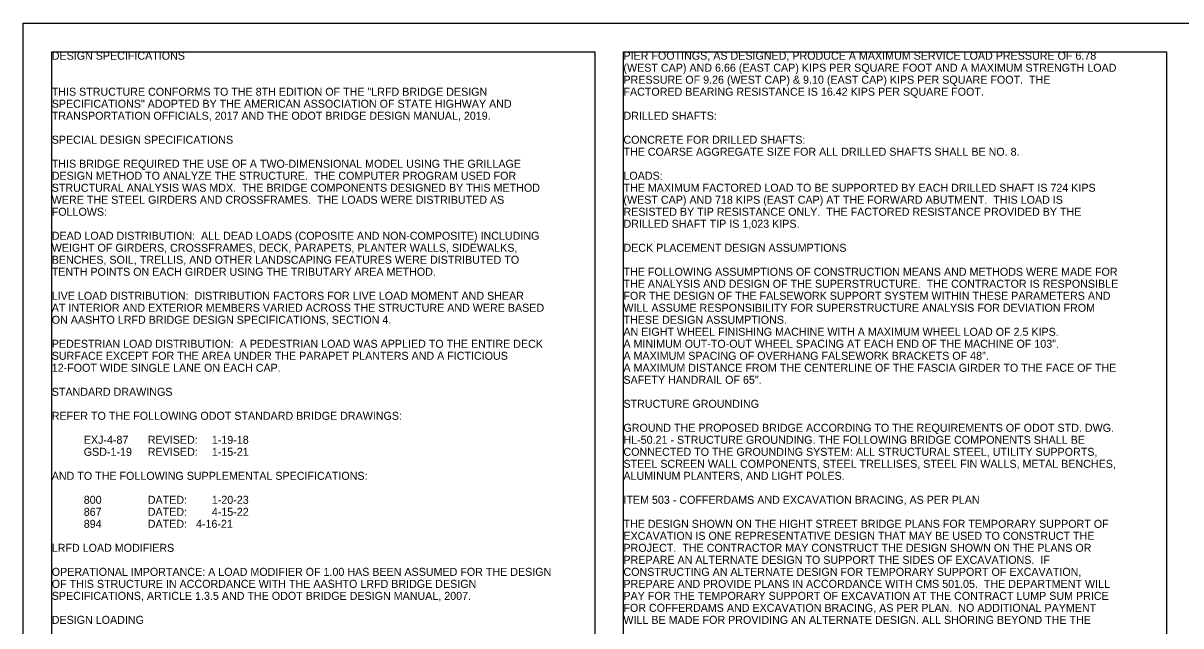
# Model space of a CAD drawing. Extents: x -27.4 to 41.5, y -43.2 to 24.4.
# Drawn here: x 1.24 to 21.49, y 8.71 to 19.26 of the extents above; entities that cross this region are included whole.
import ezdxf

# ---------------------------------------------------------------- set-up
doc = ezdxf.new("R2010")
doc.units = 0
for name, color, linetype in [('BR_P_Slab_Object', 7, 'Continuous'), ('BR_P_Sub_Foot_Hidden', 7, 'Continuous'), ('Default', 7, 'Continuous'), ('SH_Data', 7, 'Continuous')]:
    doc.layers.add(name, color=color, linetype=linetype)

msp = doc.modelspace()

# ---------------------------------------------------------------- linework, layer by layer
at = {"layer": 'BR_P_Slab_Object'}
for points in [[(1.744, 18.759), (11.244, 18.759), (11.244, -1.241), (1.744, -1.241)], [(11.744, 18.759), (21.244, 18.759), (21.244, -1.241), (11.744, -1.241)]]:
    msp.add_lwpolyline(points, close=True, dxfattribs=at)
at = {"layer": 'SH_Data'}
msp.add_lwpolyline([(1.244, 19.259), (31.744, 19.259), (31.744, -1.741), (1.244, -1.741)], close=True, dxfattribs=at)

# ---------------------------------------------------------------- texts
at = {"layer": 'BR_P_Sub_Foot_Hidden'}
for s, p in [('DESIGN SPECIFICATIONS', (1.744, 18.619)), ('PIER FOOTINGS, AS DESIGNED, PRODUCE A MAXIMUM SERVICE LOAD PRESSURE OF 6.78 ', (11.744, 18.619)), ('(WEST CAP) AND 6.66 (EAST CAP) KIPS PER SQUARE FOOT AND A MAXIMUM STRENGTH LOAD ', (11.744, 18.409)), ('PRESSURE OF 9.26 (WEST CAP) & 9.10 (EAST CAP) KIPS PER SQUARE FOOT.  THE ', (11.744, 18.199)), ('THIS STRUCTURE CONFORMS TO THE 8TH EDITION OF THE "LRFD BRIDGE DESIGN ', (1.744, 17.989)), ('FACTORED BEARING RESISTANCE IS 16.42 KIPS PER SQUARE FOOT.', (11.744, 17.989)), ('SPECIFICATIONS" ADOPTED BY THE AMERICAN ASSOCIATION OF STATE HIGHWAY AND ', (1.744, 17.779)), ('TRANSPORTATION OFFICIALS, 2017 AND THE ODOT BRIDGE DESIGN MANUAL, 2019.', (1.744, 17.569)), ('DRILLED SHAFTS:', (11.744, 17.569)), ('DRILLED SHAFTS:', (11.744, 17.569)), ('SPECIAL DESIGN SPECIFICATIONS', (1.744, 17.149)), ('SPECIAL DESIGN SPECIFICATIONS', (1.744, 17.149)), ('CONCRETE FOR DRILLED SHAFTS:', (11.744, 17.149)), ('THE COARSE AGGREGATE SIZE FOR ALL DRILLED SHAFTS SHALL BE NO. 8.', (11.744, 16.939)), ('THIS BRIDGE REQUIRED THE USE OF A TWO-DIMENSIONAL MODEL USING THE GRILLAGE ', (1.744, 16.729)), ('DESIGN METHOD TO ANALYZE THE STRUCTURE.  THE COMPUTER PROGRAM USED FOR ', (1.744, 16.519)), ('LOADS:', (11.744, 16.519)), ('STRUCTURAL ANALYSIS WAS MDX.  THE BRIDGE COMPONENTS DESIGNED BY THIS METHOD ', (1.744, 16.309)), ('THE MAXIMUM FACTORED LOAD TO BE SUPPORTED BY EACH DRILLED SHAFT IS 724 KIPS ', (11.744, 16.309)), ('WERE THE STEEL GIRDERS AND CROSSFRAMES.  THE LOADS WERE DISTRIBUTED AS ', (1.744, 16.099)), ('(WEST CAP) AND 718 KIPS (EAST CAP) AT THE FORWARD ABUTMENT.  THIS LOAD IS ', (11.744, 16.099)), ('FOLLOWS:', (1.744, 15.889)), ('RESISTED BY TIP RESISTANCE ONLY.  THE FACTORED RESISTANCE PROVIDED BY THE ', (11.744, 15.889)), ('DRILLED SHAFT TIP IS 1,023 KIPS.', (11.744, 15.679)), ('DEAD LOAD DISTRIBUTION:  ALL DEAD LOADS (COPOSITE AND NON-COMPOSITE) INCLUDING ', (1.744, 15.469)), ('WEIGHT OF GIRDERS, CROSSFRAMES, DECK, PARAPETS, PLANTER WALLS, SIDEWALKS, ', (1.744, 15.259)), ('DECK PLACEMENT DESIGN ASSUMPTIONS', (11.744, 15.259)), ('DECK PLACEMENT DESIGN ASSUMPTIONS', (11.744, 15.259)), ('BENCHES, SOIL, TRELLIS, AND OTHER LANDSCAPING FEATURES WERE DISTRIBUTED TO ', (1.744, 15.049)), ('TENTH POINTS ON EACH GIRDER USING THE TRIBUTARY AREA METHOD.  ', (1.744, 14.839)), ('THE FOLLOWING ASSUMPTIONS OF CONSTRUCTION MEANS AND METHODS WERE MADE FOR ', (11.744, 14.839)), ('THE ANALYSIS AND DESIGN OF THE SUPERSTRUCTURE.  THE CONTRACTOR IS RESPONSIBLE ', (11.744, 14.629)), ('LIVE LOAD DISTRIBUTION:  DISTRIBUTION FACTORS FOR LIVE LOAD MOMENT AND SHEAR ', (1.744, 14.419)), ('FOR THE DESIGN OF THE FALSEWORK SUPPORT SYSTEM WITHIN THESE PARAMETERS AND ', (11.744, 14.419)), ('AT INTERIOR AND EXTERIOR MEMBERS VARIED ACROSS THE STRUCTURE AND WERE BASED ', (1.744, 14.209)), ('WILL ASSUME RESPONSIBILITY FOR SUPERSTRUCTURE ANALYSIS FOR DEVIATION FROM ', (11.744, 14.209)), ('ON AASHTO LRFD BRIDGE DESIGN SPECIFICATIONS, SECTION 4.  ', (1.744, 13.999)), ('THESE DESIGN ASSUMPTIONS.', (11.744, 13.999)), ('AN EIGHT WHEEL FINISHING MACHINE WITH A MAXIMUM WHEEL LOAD OF 2.5 KIPS.', (11.744, 13.789)), ('PEDESTRIAN LOAD DISTRIBUTION:  A PEDESTRIAN LOAD WAS APPLIED TO THE ENTIRE DECK ', (1.744, 13.579)), ('A MINIMUM OUT-TO-OUT WHEEL SPACING AT EACH END OF THE MACHINE OF 103".', (11.744, 13.579)), ('SURFACE EXCEPT FOR THE AREA UNDER THE PARAPET PLANTERS AND A FICTICIOUS ', (1.744, 13.369)), ('A MAXIMUM SPACING OF OVERHANG FALSEWORK BRACKETS OF 48".', (11.744, 13.369)), ('12-FOOT WIDE SINGLE LANE ON EACH CAP.', (1.744, 13.159)), ('A MAXIMUM DISTANCE FROM THE CENTERLINE OF THE FASCIA GIRDER TO THE FACE OF THE ', (11.744, 13.159)), ('SAFETY HANDRAIL OF 65".', (11.744, 12.949)), ('STANDARD DRAWINGS', (1.744, 12.739)), ('STANDARD DRAWINGS', (1.744, 12.739)), ('STRUCTURE GROUNDING', (11.744, 12.529)), ('STRUCTURE GROUNDING', (11.744, 12.529)), ('REFER TO THE FOLLOWING ODOT STANDARD BRIDGE DRAWINGS:', (1.744, 12.319)), ('GROUND THE PROPOSED BRIDGE ACCORDING TO THE REQUIREMENTS OF ODOT STD. DWG. ', (11.744, 12.109)), ('EXJ-4-87 ', (2.304, 11.899)), ('REVISED: ', (3.424, 11.899)), ('1-19-18', (4.544, 11.899)), ('HL-50.21 - STRUCTURE GROUNDING. THE FOLLOWING BRIDGE COMPONENTS SHALL BE ', (11.744, 11.899)), ('GSD-1-19 ', (2.304, 11.689)), ('REVISED: ', (3.424, 11.689)), ('1-15-21', (4.544, 11.689)), ('CONNECTED TO THE GROUNDING SYSTEM: ALL STRUCTURAL STEEL, UTILITY SUPPORTS, ', (11.744, 11.689)), ('STEEL SCREEN WALL COMPONENTS, STEEL TRELLISES, STEEL FIN WALLS, METAL BENCHES, ', (11.744, 11.479)), ('AND TO THE FOLLOWING SUPPLEMENTAL SPECIFICATIONS:', (1.744, 11.269)), ('ALUMINUM PLANTERS, AND LIGHT POLES. ', (11.744, 11.269)), ('800', (2.304, 10.849)), ('DATED:', (3.424, 10.849)), ('1-20-23', (4.544, 10.849)), ('ITEM 503 - COFFERDAMS AND EXCAVATION BRACING, AS PER PLAN', (11.744, 10.849)), ('ITEM 503 - COFFERDAMS AND EXCAVATION BRACING, AS PER PLAN', (11.744, 10.849)), ('867', (2.304, 10.639)), ('DATED: ', (3.424, 10.639)), ('4-15-22', (4.544, 10.639)), ('894 ', (2.304, 10.429)), ('DATED:   4-16-21 ', (3.424, 10.429)), ('THE DESIGN SHOWN ON THE HIGHT STREET BRIDGE PLANS FOR TEMPORARY SUPPORT OF ', (11.744, 10.429)), ('EXCAVATION IS ONE REPRESENTATIVE DESIGN THAT MAY BE USED TO CONSTRUCT THE ', (11.744, 10.219)), ('LRFD LOAD MODIFIERS', (1.744, 10.009)), ('LRFD LOAD MODIFIERS', (1.744, 10.009)), ('PROJECT.  THE CONTRACTOR MAY CONSTRUCT THE DESIGN SHOWN ON THE PLANS OR ', (11.744, 10.009)), ('PREPARE AN ALTERNATE DESIGN TO SUPPORT THE SIDES OF EXCAVATIONS.  IF ', (11.744, 9.799)), ('OPERATIONAL IMPORTANCE: A LOAD MODIFIER OF 1.00 HAS BEEN ASSUMED FOR THE DESIGN ', (1.744, 9.589)), ('CONSTRUCTING AN ALTERNATE DESIGN FOR TEMPORARY SUPPORT OF EXCAVATION, ', (11.744, 9.589)), ('OF THIS STRUCTURE IN ACCORDANCE WITH THE AASHTO LRFD BRIDGE DESIGN ', (1.744, 9.379)), ('PREPARE AND PROVIDE PLANS IN ACCORDANCE WITH CMS 501.05.  THE DEPARTMENT WILL ', (11.744, 9.379)), ('SPECIFICATIONS, ARTICLE 1.3.5 AND THE ODOT BRIDGE DESIGN MANUAL, 2007.', (1.744, 9.169)), ('PAY FOR THE TEMPORARY SUPPORT OF EXCAVATION AT THE CONTRACT LUMP SUM PRICE ', (11.744, 9.169)), ('FOR COFFERDAMS AND EXCAVATION BRACING, AS PER PLAN.  NO ADDITIONAL PAYMENT ', (11.744, 8.959)), ('DESIGN LOADING', (1.744, 8.749)), ('DESIGN LOADING', (1.744, 8.749)), ('WILL BE MADE FOR PROVIDING AN ALTERNATE DESIGN. ALL SHORING BEYOND THE THE ', (11.744, 8.749))]:
    msp.add_text(s, height=0.14, dxfattribs=at).set_placement(p)
at = {"layer": 'Default'}
msp.add_text('DESIGN SPECIFICATIONS', height=0.14, dxfattribs=at).set_placement((1.744, 18.619))

doc.saveas('drawing.dxf')
